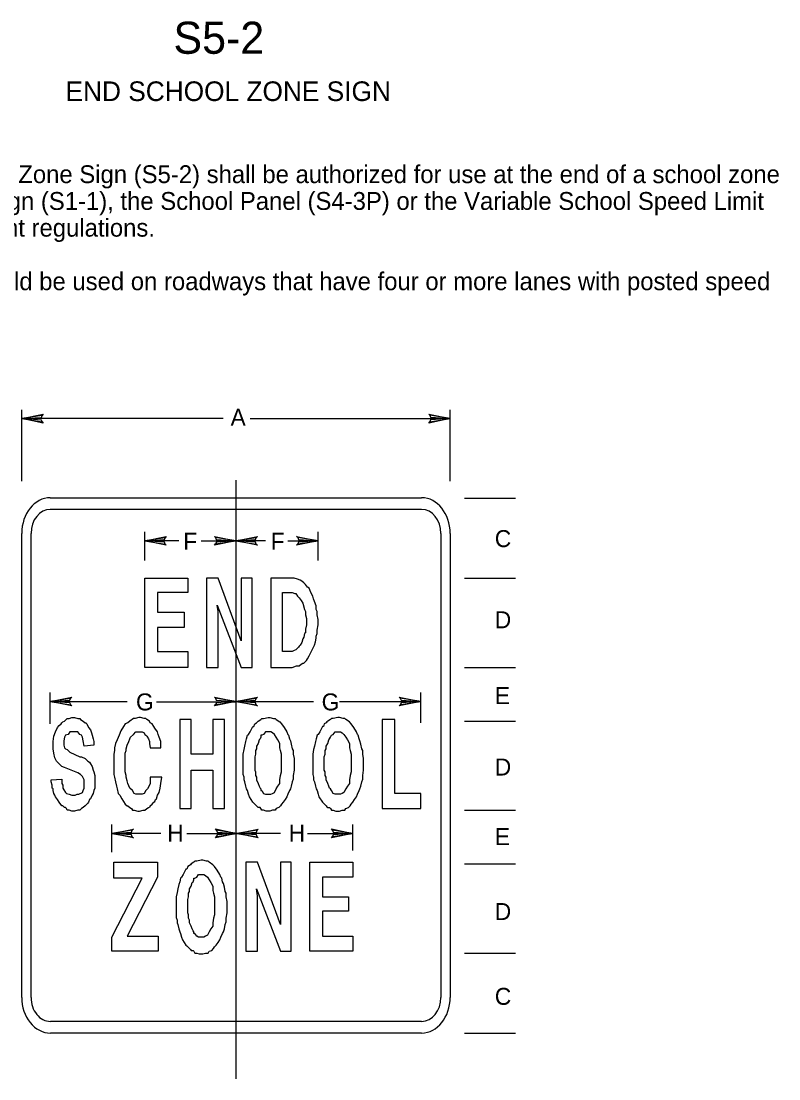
# Model space of a CAD drawing. Extents: x 0.012 to 0.188, y 0.004 to 0.259.
# Drawn here: x 0.0817 to 0.1878, y 0.111 to 0.2592 of the extents above; entities that cross this region are included whole.
import ezdxf

# ---------------------------------------------------------------- set-up
doc = ezdxf.new("R2010")
doc.units = 0
for name, color, linetype in [('1', 7, 'Continuous'), ('2', 7, 'Continuous'), ('3', 7, 'Continuous')]:
    doc.layers.add(name, color=color, linetype=linetype)

# ---------------------------------------------------------------- blocks, each defined once
blk = doc.blocks.new('RARROW')
at = {"layer": '3'}
for p, q in [((-2.156, 0.285), (-2.2665, 0.384625)), ((-2.2665, 0.384625), (0, 0)), ((0, 0), (-2.2665, -0.379125)), ((-2.156, 0.285), (-2.075625, 0.12075)), ((0, 0), (-2.156, 0.285)), ((-2.14975, -0.2705), (0, 0)), ((-2.075625, 0.12075), (0, 0)), ((0, 0), (-2.074, -0.108)), ((-2.2665, -0.379125), (-2.14975, -0.2705)), ((-2.074, -0.108), (-2.14975, -0.2705))]:
    blk.add_line(p, q, dxfattribs=at)

msp = doc.modelspace()

# ---------------------------------------------------------------- linework, layer by layer
at = {"layer": '1'}
msp.add_line((0.11175, 0.19487), (0.11175, 0.111), dxfattribs=at)
msp.add_lwpolyline([(0.10388, 0.14888), (0.1055, 0.14888)], dxfattribs=at)
at = {"layer": '3'}
for p, q in [((0.08175, 0.19475), (0.08175, 0.20475)), ((0.14175, 0.19475), (0.14175, 0.20475)), ((0.10995, 0.20352), (0.08175, 0.20352)), ((0.11376, 0.20352), (0.14175, 0.20352)), ((0.08575, 0.19242), (0.13775, 0.19242)), ((0.14375, 0.19237), (0.15088, 0.19237)), ((0.08575, 0.1908), (0.13775, 0.1908)), ((0.08175, 0.12242), (0.08175, 0.18742)), ((0.08305, 0.12242), (0.08305, 0.18742)), ((0.099, 0.18363), (0.099, 0.18763)), ((0.12325, 0.18363), (0.12325, 0.18763)), ((0.14045, 0.18742), (0.14045, 0.12242)), ((0.14175, 0.18742), (0.14175, 0.12242)), ((0.10375, 0.18638), (0.099, 0.18638)), ((0.10687, 0.18638), (0.11175, 0.18638)), ((0.11588, 0.18638), (0.11175, 0.18638)), ((0.11175, 0.18538), (0.11175, 0.18513)), ((0.119, 0.18638), (0.12325, 0.18638)), ((0.14375, 0.18113), (0.15088, 0.18113)), ((0.11175, 0.16762), (0.11175, 0.16512)), ((0.14375, 0.16862), (0.15088, 0.16862)), ((0.08575, 0.16075), (0.08575, 0.16512)), ((0.13762, 0.16087), (0.13762, 0.16512)), ((0.0965, 0.16383), (0.08575, 0.16383)), ((0.10063, 0.16383), (0.11175, 0.16383)), ((0.12262, 0.16383), (0.11175, 0.16383)), ((0.12625, 0.16387), (0.13762, 0.16387)), ((0.14375, 0.16112), (0.15088, 0.16112)), ((0.14375, 0.14863), (0.15088, 0.14863)), ((0.09438, 0.14275), (0.09438, 0.14663)), ((0.10125, 0.14539), (0.09438, 0.14539)), ((0.10487, 0.14539), (0.11188, 0.14539)), ((0.118, 0.14539), (0.11188, 0.14539)), ((0.12175, 0.14539), (0.12812, 0.14539)), ((0.12812, 0.143), (0.12812, 0.14663)), ((0.14375, 0.14113), (0.15088, 0.14113)), ((0.14375, 0.12862), (0.15088, 0.12862)), ((0.13775, 0.11905), (0.08576, 0.11905)), ((0.13775, 0.11742), (0.08576, 0.11742)), ((0.14375, 0.11738), (0.15088, 0.11738))]:
    msp.add_line(p, q, dxfattribs=at)
for points in [[(0.099, 0.16862), (0.099, 0.18113), (0.105, 0.18113), (0.105, 0.17913), (0.10075, 0.17913), (0.10075, 0.17638), (0.1045, 0.17638), (0.1045, 0.17425), (0.10075, 0.17425), (0.10075, 0.17087), (0.105, 0.17087), (0.105, 0.16862), (0.099, 0.16862)], [(0.10762, 0.18113), (0.10762, 0.16862), (0.10925, 0.16862), (0.10925, 0.1765), (0.10912, 0.17738), (0.1125, 0.16862), (0.114, 0.16862), (0.114, 0.18113), (0.1125, 0.18113), (0.1125, 0.17388), (0.1125, 0.17238), (0.10925, 0.18113), (0.10762, 0.18113)], [(0.11963, 0.18113), (0.11663, 0.18113), (0.11663, 0.16862), (0.11963, 0.16862)], [(0.11963, 0.16862), (0.12025, 0.16887), (0.12062, 0.16887), (0.12087, 0.16912), (0.12112, 0.16925), (0.12125, 0.16925), (0.12162, 0.16962), (0.12175, 0.16987), (0.122, 0.17025), (0.12225, 0.17075), (0.12237, 0.171), (0.12262, 0.1715), (0.12275, 0.17175), (0.12287, 0.17225), (0.123, 0.17275), (0.123, 0.173), (0.12312, 0.17338), (0.12312, 0.17388), (0.12325, 0.17463), (0.12325, 0.17488), (0.12325, 0.17538), (0.12312, 0.176), (0.12312, 0.1765), (0.123, 0.17675), (0.123, 0.17725), (0.12275, 0.17788), (0.12262, 0.17825), (0.1225, 0.17863), (0.12225, 0.17913), (0.12212, 0.1795), (0.122, 0.17975), (0.12175, 0.17988), (0.1215, 0.18025), (0.12125, 0.1805), (0.121, 0.18075), (0.12075, 0.18088), (0.12037, 0.181), (0.11988, 0.18113), (0.11963, 0.18113)], [(0.11963, 0.17087), (0.11825, 0.17087), (0.11825, 0.17913), (0.11963, 0.17913)], [(0.11963, 0.17913), (0.11963, 0.17913), (0.12, 0.179), (0.12012, 0.179), (0.12037, 0.17863), (0.12062, 0.17838), (0.12087, 0.178), (0.12112, 0.17763), (0.12137, 0.17675), (0.1215, 0.1765), (0.1215, 0.176), (0.12162, 0.1755), (0.12162, 0.17488), (0.12162, 0.17463), (0.1215, 0.174), (0.1215, 0.1735), (0.12137, 0.17338), (0.12125, 0.17288), (0.12112, 0.17263), (0.121, 0.17213), (0.12075, 0.17175), (0.12062, 0.17162), (0.1205, 0.1715), (0.12012, 0.17112), (0.11988, 0.171), (0.11963, 0.17087)], [(0.087, 0.1605), (0.08725, 0.16075), (0.08738, 0.16087), (0.0875, 0.161), (0.08775, 0.16112), (0.08812, 0.1615), (0.08837, 0.1615), (0.08875, 0.16162), (0.08887, 0.16162), (0.08912, 0.16162), (0.08962, 0.1615), (0.08987, 0.1615), (0.09, 0.16137), (0.09037, 0.16112), (0.09062, 0.16087), (0.09075, 0.16087), (0.09087, 0.16075)], [(0.10125, 0.15738), (0.10125, 0.15825), (0.101, 0.15888), (0.10088, 0.15925), (0.10075, 0.15963), (0.10038, 0.16012), (0.10025, 0.16037), (0.1, 0.16075), (0.09975, 0.16087), (0.09963, 0.16112), (0.09925, 0.16137), (0.09913, 0.1615), (0.09888, 0.1615), (0.09838, 0.16162), (0.09813, 0.16162), (0.09763, 0.1615), (0.09738, 0.1615), (0.09688, 0.16112), (0.09663, 0.16087), (0.09625, 0.16075), (0.096, 0.16037), (0.09563, 0.15975), (0.09538, 0.15913), (0.09513, 0.1585), (0.09488, 0.158), (0.09475, 0.15738), (0.09475, 0.157), (0.09463, 0.1565), (0.09463, 0.156), (0.09463, 0.15538)], [(0.11275, 0.15513), (0.11275, 0.15538), (0.11275, 0.15588), (0.11275, 0.1565), (0.11288, 0.15713), (0.113, 0.15763), (0.11313, 0.15825), (0.11325, 0.15863), (0.11338, 0.15913), (0.1135, 0.15925), (0.11375, 0.15963), (0.11413, 0.16037), (0.11425, 0.16037), (0.11438, 0.16075), (0.11463, 0.16087), (0.11475, 0.161), (0.11488, 0.16112), (0.11525, 0.16137), (0.11538, 0.1615), (0.11563, 0.1615), (0.11625, 0.16162)], [(0.11625, 0.16162), (0.1165, 0.16162), (0.117, 0.1615), (0.11725, 0.1615), (0.11738, 0.16137), (0.11788, 0.161), (0.11813, 0.16075), (0.1185, 0.16025), (0.11888, 0.15963), (0.119, 0.15925), (0.11913, 0.15913), (0.11925, 0.15863), (0.11938, 0.15838), (0.1195, 0.15788), (0.11963, 0.15725), (0.11975, 0.157), (0.11975, 0.1565), (0.11988, 0.15588), (0.11988, 0.1555), (0.11988, 0.15513)], [(0.126, 0.16162), (0.12538, 0.1615), (0.12513, 0.1615), (0.125, 0.16137), (0.12462, 0.16112), (0.1245, 0.161), (0.12437, 0.16087), (0.12412, 0.16075), (0.124, 0.16037), (0.12387, 0.16037), (0.1235, 0.15963), (0.12325, 0.15925), (0.12312, 0.15913), (0.123, 0.15863), (0.12287, 0.15825), (0.12275, 0.15763), (0.12262, 0.15713), (0.1225, 0.1565), (0.1225, 0.15588), (0.1225, 0.15538), (0.1225, 0.15513)], [(0.12962, 0.15513), (0.12962, 0.1555), (0.12962, 0.15588), (0.1295, 0.1565), (0.1295, 0.157), (0.12937, 0.15725), (0.12925, 0.15788), (0.12912, 0.15838), (0.129, 0.15863), (0.12887, 0.15913), (0.12875, 0.15925), (0.12862, 0.15963), (0.12825, 0.16025), (0.12788, 0.16075), (0.12763, 0.161), (0.12713, 0.16137), (0.127, 0.1615), (0.12675, 0.1615), (0.12625, 0.16162), (0.126, 0.16162)], [(0.0905, 0.15213), (0.0905, 0.15238), (0.0905, 0.15288), (0.09025, 0.15338), (0.09, 0.15363), (0.08962, 0.15388), (0.08775, 0.15463), (0.08738, 0.15475), (0.08688, 0.15525), (0.08663, 0.1555), (0.08638, 0.156), (0.08625, 0.15663), (0.08613, 0.15725), (0.08613, 0.15825), (0.08625, 0.159), (0.0865, 0.15963), (0.08675, 0.16025), (0.087, 0.1605)], [(0.09087, 0.16075), (0.09112, 0.16025), (0.09137, 0.15988), (0.0915, 0.1595), (0.09162, 0.15913), (0.09175, 0.15863), (0.09187, 0.15825), (0.09187, 0.15775), (0.0905, 0.15763)], [(0.10388, 0.16137), (0.10388, 0.14888), (0.1055, 0.14888), (0.1055, 0.15425), (0.1085, 0.15425), (0.1085, 0.14888), (0.11013, 0.14888), (0.11013, 0.16137), (0.1085, 0.16137), (0.1085, 0.1565), (0.1055, 0.1565), (0.1055, 0.16137), (0.10388, 0.16137)], [(0.13225, 0.16137), (0.13225, 0.14888), (0.13762, 0.14888), (0.13762, 0.151), (0.134, 0.151), (0.134, 0.16137), (0.13225, 0.16137)], [(0.0905, 0.15763), (0.09037, 0.15838), (0.09025, 0.15888), (0.09012, 0.15913), (0.08987, 0.15925), (0.08962, 0.15963), (0.08925, 0.15963), (0.08887, 0.15963), (0.08862, 0.15963), (0.0885, 0.15963), (0.08825, 0.15925), (0.08788, 0.15913), (0.08775, 0.15888), (0.08763, 0.15838), (0.08763, 0.158)], [(0.09625, 0.1555), (0.09625, 0.156), (0.09625, 0.15663), (0.09638, 0.157), (0.09638, 0.15725), (0.0965, 0.15775), (0.09675, 0.15825), (0.09688, 0.15863), (0.097, 0.15888), (0.09738, 0.15925), (0.09775, 0.15963), (0.09825, 0.15963), (0.09838, 0.15963), (0.09863, 0.15963), (0.09888, 0.1595), (0.099, 0.15925), (0.09913, 0.15913), (0.09925, 0.159), (0.0995, 0.15863), (0.09963, 0.15825), (0.09963, 0.158), (0.09975, 0.15738)], [(0.11638, 0.15963), (0.11613, 0.15963), (0.11588, 0.15963), (0.11563, 0.15925), (0.11538, 0.15913), (0.11525, 0.15913), (0.11525, 0.15888), (0.11513, 0.15863), (0.115, 0.1585), (0.11488, 0.158), (0.11463, 0.15763), (0.11463, 0.15725), (0.1145, 0.157), (0.1145, 0.1565), (0.11438, 0.15613), (0.11438, 0.15588), (0.11438, 0.15538), (0.11438, 0.15525)], [(0.11813, 0.15525), (0.11813, 0.15538), (0.11813, 0.15588), (0.11813, 0.1565), (0.118, 0.157), (0.11788, 0.15738), (0.11788, 0.158), (0.11763, 0.1585), (0.11738, 0.15888), (0.11713, 0.15925), (0.11688, 0.1595), (0.11663, 0.15963), (0.1165, 0.15963), (0.11638, 0.15963)], [(0.12412, 0.15525), (0.12412, 0.15538), (0.12412, 0.15588), (0.12412, 0.15613), (0.12425, 0.1565), (0.12425, 0.157), (0.12437, 0.15725), (0.12437, 0.15763), (0.12462, 0.158), (0.12475, 0.1585), (0.12487, 0.15863), (0.125, 0.15888), (0.12513, 0.15913), (0.12513, 0.15913), (0.12538, 0.15925), (0.12563, 0.15963), (0.12588, 0.15963), (0.12613, 0.15963)], [(0.12613, 0.15963), (0.12625, 0.15963), (0.12638, 0.15963), (0.12663, 0.1595), (0.12688, 0.15925), (0.12713, 0.15888), (0.12738, 0.1585), (0.12763, 0.158), (0.12763, 0.15738), (0.12775, 0.157), (0.12788, 0.1565), (0.12788, 0.15588), (0.12788, 0.15538), (0.12788, 0.15525)], [(0.08763, 0.158), (0.08763, 0.15775), (0.08775, 0.15738), (0.08788, 0.15725), (0.08812, 0.15713), (0.0885, 0.15675), (0.08987, 0.15613), (0.09012, 0.15613), (0.09062, 0.15588), (0.091, 0.1555), (0.09125, 0.15538), (0.09137, 0.15513), (0.09162, 0.15475), (0.09175, 0.15425), (0.09187, 0.154), (0.092, 0.1535), (0.092, 0.153), (0.092, 0.15275), (0.092, 0.15225), (0.092, 0.15175), (0.09187, 0.15138), (0.09187, 0.15138)], [(0.09975, 0.15738), (0.10125, 0.15738)], [(0.09463, 0.15538), (0.09463, 0.1545), (0.09463, 0.15363), (0.09475, 0.15325), (0.09488, 0.15263), (0.095, 0.152), (0.09513, 0.15163), (0.09525, 0.151), (0.0955, 0.15075), (0.09575, 0.15025), (0.096, 0.14988), (0.09625, 0.1495), (0.0965, 0.14925), (0.09663, 0.14925), (0.09688, 0.149), (0.09713, 0.14888), (0.09725, 0.14863), (0.0975, 0.14863), (0.098, 0.1485), (0.09825, 0.1485), (0.09875, 0.14863), (0.099, 0.14863), (0.09925, 0.14888), (0.0995, 0.149), (0.09975, 0.14913), (0.09975, 0.14925), (0.1, 0.1495), (0.10025, 0.14975), (0.10038, 0.14988), (0.1005, 0.15013), (0.10063, 0.15025), (0.10075, 0.15075), (0.101, 0.15113), (0.10113, 0.15175), (0.10125, 0.15238), (0.10138, 0.15325)], [(0.09975, 0.15325), (0.09975, 0.15238), (0.09963, 0.15213), (0.09938, 0.15163), (0.09913, 0.15138), (0.09888, 0.151), (0.09863, 0.15088), (0.09825, 0.15088), (0.09813, 0.15088), (0.09775, 0.15088), (0.0975, 0.151), (0.09725, 0.15138), (0.09688, 0.15175), (0.09663, 0.15238), (0.0965, 0.15275), (0.09638, 0.15325), (0.09638, 0.1535), (0.09625, 0.154), (0.09625, 0.15463), (0.09625, 0.15488), (0.09625, 0.15538), (0.09625, 0.1555)], [(0.11988, 0.15513), (0.11988, 0.15425), (0.11975, 0.1535), (0.11975, 0.153), (0.11963, 0.15263), (0.1195, 0.152), (0.11938, 0.15163), (0.11925, 0.15138), (0.119, 0.15088), (0.11888, 0.1505), (0.11863, 0.15013), (0.11838, 0.14975), (0.11813, 0.1495), (0.118, 0.14925), (0.11775, 0.149), (0.11738, 0.14888), (0.11725, 0.14863), (0.11688, 0.14863), (0.1165, 0.1485), (0.11638, 0.1485), (0.116, 0.1485), (0.11563, 0.14863), (0.11538, 0.14863), (0.11525, 0.14888), (0.11513, 0.149), (0.11488, 0.149), (0.11475, 0.14913), (0.11463, 0.14925), (0.11425, 0.14963), (0.11413, 0.14975), (0.11363, 0.1505), (0.1135, 0.15088), (0.11338, 0.15138), (0.11325, 0.15163), (0.11313, 0.152), (0.113, 0.15263), (0.11288, 0.15288), (0.11288, 0.15325), (0.11275, 0.15363), (0.11275, 0.15425), (0.11275, 0.15475), (0.11275, 0.15513)], [(0.11438, 0.15525), (0.11438, 0.15513), (0.11438, 0.15463), (0.11438, 0.15425), (0.1145, 0.154), (0.1145, 0.1535), (0.11463, 0.15325), (0.11463, 0.15288), (0.11488, 0.15238), (0.115, 0.152), (0.11513, 0.15175), (0.11525, 0.15163), (0.11525, 0.15138), (0.11538, 0.15138), (0.11563, 0.151), (0.11588, 0.15088), (0.11613, 0.15088), (0.11638, 0.15088)], [(0.11638, 0.15088), (0.1165, 0.15088), (0.11663, 0.15088), (0.11688, 0.151), (0.11713, 0.15113), (0.11738, 0.15163), (0.11763, 0.152), (0.11788, 0.15238), (0.11788, 0.15288), (0.118, 0.1535), (0.11813, 0.154), (0.11813, 0.15463), (0.11813, 0.15513), (0.11813, 0.15525)], [(0.1225, 0.15513), (0.1225, 0.15475), (0.1225, 0.15425), (0.1225, 0.15363), (0.12262, 0.15325), (0.12262, 0.15288), (0.12275, 0.15263), (0.12287, 0.152), (0.123, 0.15163), (0.12312, 0.15138), (0.12325, 0.15088), (0.12337, 0.1505), (0.12387, 0.14975), (0.124, 0.14963), (0.12437, 0.14925), (0.1245, 0.14913), (0.12462, 0.149), (0.12487, 0.149), (0.125, 0.14888), (0.12513, 0.14863), (0.12538, 0.14863), (0.12575, 0.1485), (0.12613, 0.1485), (0.12625, 0.1485), (0.12663, 0.14863), (0.127, 0.14863), (0.12713, 0.14888), (0.1275, 0.149), (0.12775, 0.14925), (0.12788, 0.1495), (0.12812, 0.14975), (0.12837, 0.15013), (0.12862, 0.1505), (0.12875, 0.15088), (0.129, 0.15138), (0.12912, 0.15163), (0.12925, 0.152), (0.12937, 0.15263), (0.1295, 0.153), (0.1295, 0.1535), (0.12962, 0.15425), (0.12962, 0.15513)], [(0.12613, 0.15088), (0.12588, 0.15088), (0.12563, 0.15088), (0.12538, 0.151), (0.12513, 0.15138), (0.12513, 0.15138), (0.125, 0.15163), (0.12487, 0.15175), (0.12475, 0.152), (0.12462, 0.15238), (0.12437, 0.15288), (0.12437, 0.15325), (0.12425, 0.1535), (0.12425, 0.154), (0.12412, 0.15425), (0.12412, 0.15463), (0.12412, 0.15513), (0.12412, 0.15525)], [(0.12788, 0.15525), (0.12788, 0.15513), (0.12788, 0.15463), (0.12788, 0.154), (0.12775, 0.1535), (0.12763, 0.15288), (0.12763, 0.15238), (0.12738, 0.152), (0.12713, 0.15163), (0.12688, 0.15113), (0.12663, 0.151), (0.12638, 0.15088), (0.12625, 0.15088), (0.12613, 0.15088)], [(0.08588, 0.15288), (0.08738, 0.153), (0.08738, 0.15275)], [(0.0865, 0.1505), (0.08638, 0.15075), (0.08625, 0.151), (0.08613, 0.15138), (0.08613, 0.15163), (0.086, 0.15175), (0.086, 0.15213), (0.08588, 0.15263), (0.08588, 0.15288)], [(0.08738, 0.15275), (0.08738, 0.15238), (0.0875, 0.15213), (0.0875, 0.15175), (0.08763, 0.1515), (0.08788, 0.15113), (0.088, 0.151), (0.08837, 0.15088), (0.08875, 0.15075), (0.08887, 0.15075), (0.08925, 0.15075), (0.0895, 0.15088), (0.08975, 0.15088)], [(0.10138, 0.15325), (0.09975, 0.15325)], [(0.09187, 0.15138), (0.09175, 0.151), (0.09162, 0.15075), (0.09137, 0.15025), (0.09125, 0.15013), (0.09112, 0.14975), (0.091, 0.14963), (0.09087, 0.1495), (0.09062, 0.14925), (0.09037, 0.149), (0.09012, 0.14888), (0.08987, 0.14863), (0.08962, 0.14863), (0.08912, 0.1485), (0.089, 0.1485), (0.08875, 0.1485), (0.08837, 0.14863), (0.08812, 0.14863), (0.088, 0.14888), (0.08788, 0.149), (0.08775, 0.149), (0.0875, 0.14925), (0.08738, 0.14925), (0.087, 0.14975), (0.08675, 0.15013), (0.0865, 0.1505)], [(0.08975, 0.15088), (0.09025, 0.15113), (0.09037, 0.15138), (0.0905, 0.15175), (0.0905, 0.15213)], [(0.09438, 0.12887), (0.09438, 0.13087), (0.09863, 0.13912), (0.0985, 0.13912), (0.0985, 0.13912), (0.09838, 0.13912), (0.09463, 0.13912), (0.09463, 0.14138), (0.10075, 0.14138), (0.10075, 0.13925), (0.0965, 0.131), (0.09663, 0.131), (0.09675, 0.131), (0.097, 0.131), (0.10088, 0.131), (0.10088, 0.12887), (0.09438, 0.12887)], [(0.10687, 0.14163), (0.10625, 0.1415), (0.106, 0.1415), (0.10587, 0.14138), (0.1055, 0.14113), (0.10537, 0.141), (0.10525, 0.14088), (0.105, 0.14075), (0.10487, 0.14037), (0.10475, 0.14037), (0.10437, 0.13962), (0.10412, 0.13925), (0.104, 0.13912), (0.10388, 0.13862), (0.10375, 0.13825), (0.10363, 0.13762), (0.1035, 0.13712), (0.10338, 0.1365), (0.10338, 0.13587), (0.10338, 0.13537), (0.10338, 0.13512)], [(0.1105, 0.13512), (0.1105, 0.1355), (0.1105, 0.13587), (0.11038, 0.1365), (0.11038, 0.137), (0.11025, 0.13725), (0.11013, 0.13787), (0.11, 0.13837), (0.10988, 0.13862), (0.10975, 0.13912), (0.10963, 0.13925), (0.1095, 0.13962), (0.10912, 0.14025), (0.10875, 0.14075), (0.1085, 0.141), (0.108, 0.14138), (0.10787, 0.1415), (0.10762, 0.1415), (0.10712, 0.14163), (0.10687, 0.14163)], [(0.11313, 0.14138), (0.11313, 0.12887), (0.11475, 0.12887), (0.11475, 0.13662), (0.11463, 0.13762), (0.118, 0.12887), (0.1195, 0.12887), (0.1195, 0.14138), (0.118, 0.14138), (0.118, 0.134), (0.118, 0.13262), (0.11475, 0.14138), (0.11313, 0.14138)], [(0.12212, 0.12887), (0.12212, 0.14138), (0.12812, 0.14138), (0.12812, 0.13925), (0.12387, 0.13925), (0.12387, 0.1365), (0.1275, 0.1365), (0.1275, 0.1345), (0.12387, 0.1345), (0.12387, 0.131), (0.12812, 0.131), (0.12812, 0.12887), (0.12212, 0.12887)], [(0.105, 0.13525), (0.105, 0.13537), (0.105, 0.13587), (0.105, 0.13612), (0.10512, 0.1365), (0.10512, 0.137), (0.10525, 0.13725), (0.10525, 0.13762), (0.1055, 0.138), (0.10562, 0.1385), (0.10575, 0.13862), (0.10587, 0.13887), (0.10587, 0.13912), (0.106, 0.13912), (0.10625, 0.13925), (0.1065, 0.13962), (0.10675, 0.13962), (0.107, 0.13962)], [(0.107, 0.13962), (0.10712, 0.13962), (0.10725, 0.13962), (0.1075, 0.1395), (0.10775, 0.13925), (0.108, 0.13887), (0.10825, 0.1385), (0.1085, 0.138), (0.1085, 0.13737), (0.10862, 0.137), (0.10875, 0.1365), (0.10875, 0.13587), (0.10875, 0.13537), (0.10875, 0.13525)], [(0.10338, 0.13512), (0.10338, 0.13475), (0.10338, 0.13425), (0.10338, 0.13362), (0.1035, 0.13325), (0.1035, 0.13287), (0.10363, 0.13262), (0.10375, 0.132), (0.10388, 0.13162), (0.104, 0.13137), (0.10412, 0.13087), (0.10425, 0.1305), (0.10475, 0.12975), (0.10487, 0.12962), (0.10525, 0.12925), (0.10537, 0.12912), (0.1055, 0.129), (0.10575, 0.129), (0.10587, 0.12887), (0.106, 0.12862), (0.10625, 0.12862), (0.10662, 0.1285), (0.107, 0.1285), (0.10712, 0.1285), (0.1075, 0.12862), (0.10787, 0.12862), (0.108, 0.12887), (0.10837, 0.129), (0.10862, 0.12925), (0.10875, 0.1295), (0.109, 0.12975), (0.10925, 0.13012), (0.1095, 0.1305), (0.10963, 0.13087), (0.10988, 0.13137), (0.11, 0.13162), (0.11013, 0.132), (0.11025, 0.13262), (0.11038, 0.133), (0.11038, 0.1335), (0.1105, 0.13425), (0.1105, 0.13512)], [(0.107, 0.13087), (0.10675, 0.13087), (0.1065, 0.13087), (0.10625, 0.131), (0.106, 0.13137), (0.10587, 0.13137), (0.10587, 0.13162), (0.10575, 0.13175), (0.10562, 0.132), (0.1055, 0.13237), (0.10525, 0.13287), (0.10525, 0.13325), (0.10512, 0.1335), (0.10512, 0.134), (0.105, 0.13425), (0.105, 0.13462), (0.105, 0.13512), (0.105, 0.13525)], [(0.10875, 0.13525), (0.10875, 0.13512), (0.10875, 0.13462), (0.10875, 0.134), (0.10862, 0.1335), (0.1085, 0.13287), (0.1085, 0.13237), (0.10825, 0.132), (0.108, 0.13162), (0.10775, 0.13112), (0.1075, 0.131), (0.10725, 0.13087), (0.10712, 0.13087), (0.107, 0.13087)]]:
    msp.add_lwpolyline(points, dxfattribs=at)
for centre, major_axis, start_param, end_param in [((0.08575, 0.18742), (0, -0.005), 3.141593, 4.712389), ((0.13775, 0.18742), (0, 0.005), 4.712389, 6.283185), ((0.08575, 0.18742), (0, -0.00337), 3.141593, 4.712389), ((0.13775, 0.18742), (0, 0.00337), 4.712389, 6.283185), ((0.08575, 0.12242), (0, -0.005), 4.712389, 6.285566), ((0.08575, 0.12242), (0, -0.00337), 4.712389, 6.285566), ((0.13775, 0.12242), (0, -0.005), 0, 1.570796), ((0.13775, 0.12242), (0, -0.00337), 0, 1.570796)]:
    msp.add_ellipse(centre, major_axis=major_axis, ratio=0.8, start_param=start_param, end_param=end_param, dxfattribs=at)

# ---------------------------------------------------------------- block references
at = {"layer": '3', "xscale": 0.0013236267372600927, "yscale": 0.0016366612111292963, "rotation": 180}
for p in [(0.08175, 0.2035), (0.099, 0.18638), (0.11175, 0.18638), (0.08575, 0.16387), (0.11175, 0.16387), (0.09438, 0.14538), (0.11188, 0.14538)]:
    msp.add_blockref('RARROW', p, dxfattribs=at)
at = {"layer": '3', "xscale": 0.0013236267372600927, "yscale": 0.0016366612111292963}
for p in [(0.14175, 0.2035), (0.11175, 0.18638), (0.12325, 0.18638), (0.11175, 0.16387), (0.13762, 0.16387), (0.11188, 0.14538), (0.12812, 0.14538)]:
    msp.add_blockref('RARROW', p, dxfattribs=at)

# ---------------------------------------------------------------- texts
at = {"layer": '1'}
for s, height, p in [('S5-2', 0.0045, (0.103, 0.25462)), ('END SCHOOL ZONE SIGN', 0.0027503, (0.08788, 0.248))]:
    msp.add_text(s, height=height, dxfattribs=at).set_placement(p)
at = {"layer": '2'}
for s, height, p in [('   (a) Justification.  The End School Zone Sign (S5-2) shall be authorized for use at the end of a school zone ', 0.00249975, (0.0285, 0.2365)), ('which is indicated by the School Sign (S1-1), the School Panel (S4-3P) or the Variable School Speed Limit ', 0.00249975, (0.0285, 0.23275)), ('Sign in accordance with Department regulations.', 0.0024998, (0.0285, 0.229)), ('   (b) Size.  The 36" x 48" size should be used on roadways that have four or more lanes with posted speed ', 0.00249975, (0.0285, 0.2215))]:
    msp.add_text(s, height=height, dxfattribs=at).set_placement(p)
at = {"layer": '3'}
for s, p in [('A', (0.111, 0.2025)), ('F', (0.10437, 0.18513)), ('F', (0.11663, 0.18513)), ('C', (0.148, 0.1855)), ('D', (0.148, 0.17413)), ('G', (0.09775, 0.16262)), ('G', (0.12375, 0.16262)), ('E', (0.148, 0.1635)), ('D', (0.148, 0.1535)), ('H', (0.10213, 0.14425)), ('H', (0.11913, 0.14425)), ('E', (0.148, 0.14375)), ('D', (0.148, 0.13325)), ('C', (0.148, 0.12137))]:
    msp.add_text(s, height=0.00238, dxfattribs=at).set_placement(p)

doc.saveas('drawing.dxf')
